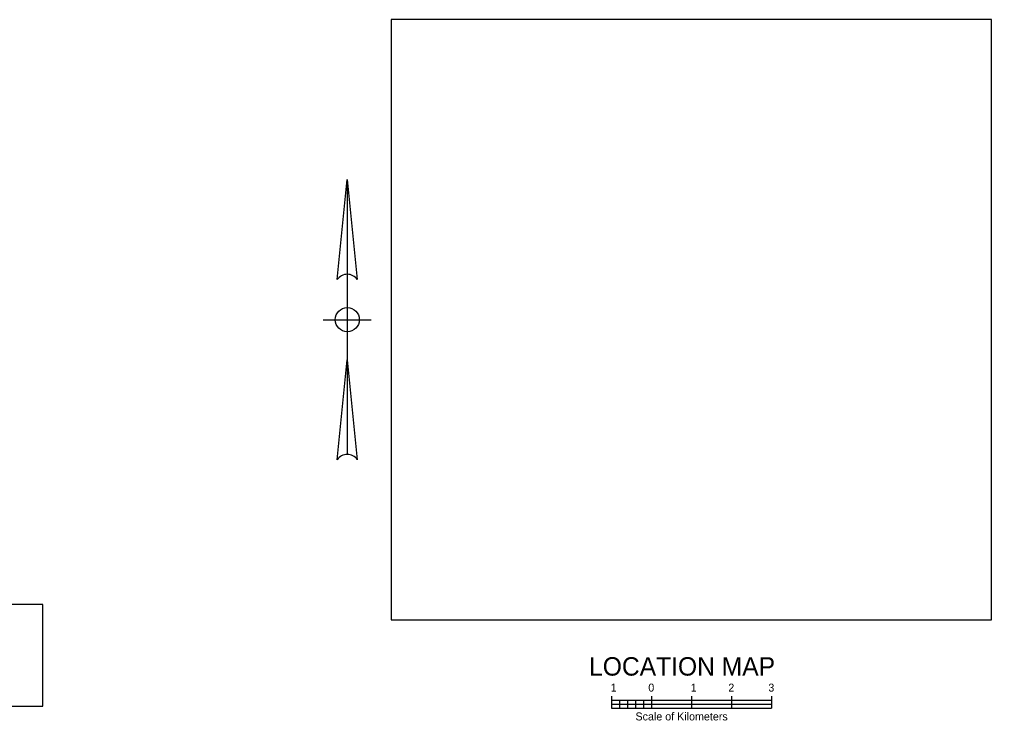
# Model space of a CAD drawing. Extents: x 605371.3 to 605398.1, y 420183.2 to 420214.1.
# Drawn here: x 605390.0858 to 605390.3288, y 420198.9816 to 420199.1567 of the extents above; entities that cross this region are included whole.
import ezdxf

# ---------------------------------------------------------------- set-up
doc = ezdxf.new("R2010")
doc.units = 0
for name, color, linetype in [('Level 1', 7, 'Continuous'), ('Notes', 7, 'Continuous'), ('Super', 7, 'Continuous')]:
    doc.layers.add(name, color=color, linetype=linetype)

msp = doc.modelspace()

# ---------------------------------------------------------------- linework, layer by layer
at = {"layer": 'Level 1'}
for p, q in [((605390.16778, 420199.11672), (605390.16778, 420199.04806)), ((605390.16778, 420199.11672), (605390.16778, 420199.04806)), ((605390.16178, 420199.08172), (605390.17378, 420199.08172)), ((605390.16178, 420199.08172), (605390.17378, 420199.08172))]:
    msp.add_line(p, q, dxfattribs=at)
for points in [[(605390.16528, 420199.09172), (605390.16778, 420199.11672), (605390.17028, 420199.09172)], [(605390.16528, 420199.09172), (605390.16778, 420199.11672), (605390.17028, 420199.09172)], [(605390.16528, 420199.04672), (605390.16778, 420199.07172), (605390.17028, 420199.04672)], [(605390.16528, 420199.04672), (605390.16778, 420199.07172), (605390.17028, 420199.04672)]]:
    msp.add_lwpolyline(points, dxfattribs=at)
msp.add_circle((605390.16778, 420199.08172), 0.003, dxfattribs=at)
msp.add_circle((605390.16778, 420199.08172), 0.003, dxfattribs=at)
for centre in [(605390.16778, 420199.09006), (605390.16778, 420199.09006), (605390.16778, 420199.04506), (605390.16778, 420199.04506)]:
    msp.add_arc(centre, 0.003, 33.5573, 146.4427, dxfattribs=at)
at = {"layer": 'Notes'}
for p, q in [((605390.32878, 420199.15672), (605390.17878, 420199.15672)), ((605390.17878, 420199.15672), (605390.17878, 420199.00672)), ((605390.32878, 420199.15672), (605390.17878, 420199.15672)), ((605390.17878, 420199.15672), (605390.17878, 420199.00672)), ((605390.32878, 420199.00672), (605390.32878, 420199.15672)), ((605390.32878, 420199.00672), (605390.32878, 420199.15672)), ((605390.17878, 420199.00672), (605390.32878, 420199.00672)), ((605390.17878, 420199.00672), (605390.32878, 420199.00672)), ((605390.23378, 420198.98767), (605390.23378, 420198.98467)), ((605390.23378, 420198.98767), (605390.23378, 420198.98467)), ((605390.24378, 420198.98767), (605390.24378, 420198.98467)), ((605390.24378, 420198.98767), (605390.24378, 420198.98467)), ((605390.25378, 420198.98767), (605390.25378, 420198.98467)), ((605390.25378, 420198.98767), (605390.25378, 420198.98467)), ((605390.26378, 420198.98767), (605390.26378, 420198.98467)), ((605390.26378, 420198.98767), (605390.26378, 420198.98467)), ((605390.27378, 420198.98767), (605390.27378, 420198.98467)), ((605390.27378, 420198.98767), (605390.27378, 420198.98467)), ((605390.23378, 420198.98667), (605390.27378, 420198.98667)), ((605390.23378, 420198.98667), (605390.27378, 420198.98667)), ((605390.23378, 420198.98567), (605390.27378, 420198.98567)), ((605390.23378, 420198.98567), (605390.27378, 420198.98567)), ((605390.23578, 420198.98667), (605390.23578, 420198.98467)), ((605390.23578, 420198.98667), (605390.23578, 420198.98467)), ((605390.23778, 420198.98667), (605390.23778, 420198.98467)), ((605390.23778, 420198.98667), (605390.23778, 420198.98467)), ((605390.23978, 420198.98667), (605390.23978, 420198.98467)), ((605390.23978, 420198.98667), (605390.23978, 420198.98467)), ((605390.24178, 420198.98667), (605390.24178, 420198.98467)), ((605390.24178, 420198.98667), (605390.24178, 420198.98467)), ((605390.23378, 420198.98467), (605390.27378, 420198.98467)), ((605390.23378, 420198.98467), (605390.27378, 420198.98467))]:
    msp.add_line(p, q, dxfattribs=at)
at = {"layer": 'Super'}
msp.add_lwpolyline([(605390.08376, 420199.01057), (605390.08376, 420198.98517), (605390.09166, 420198.98517), (605390.09166, 420199.01057)], close=True, dxfattribs=at)
msp.add_lwpolyline([(605390.08376, 420199.01057), (605390.08376, 420198.98517), (605390.09166, 420198.98517), (605390.09166, 420199.01057)], close=True, dxfattribs=at)

# ---------------------------------------------------------------- texts
at = {"layer": 'Notes'}
for s, height, p in [('LOCATION MAP', 0.0045996, (605390.2282, 420198.9928)), ('LOCATION MAP', 0.0045996, (605390.2282, 420198.9928)), ('1', 0.002, (605390.2336, 420198.9888)), ('1', 0.002, (605390.2336, 420198.9888)), ('0', 0.002, (605390.243, 420198.9888)), ('0', 0.002, (605390.243, 420198.9888)), ('1', 0.002, (605390.2536, 420198.9888)), ('1', 0.002, (605390.2536, 420198.9888)), ('2', 0.002, (605390.263, 420198.9888)), ('2', 0.002, (605390.263, 420198.9888)), ('3', 0.002, (605390.273, 420198.9888)), ('3', 0.002, (605390.273, 420198.9888)), ('Scale of Kilometers', 0.0020004, (605390.2398, 420198.9816)), ('Scale of Kilometers', 0.0020004, (605390.2398, 420198.9816))]:
    msp.add_text(s, height=height, dxfattribs=at).set_placement(p)

doc.saveas('drawing.dxf')
